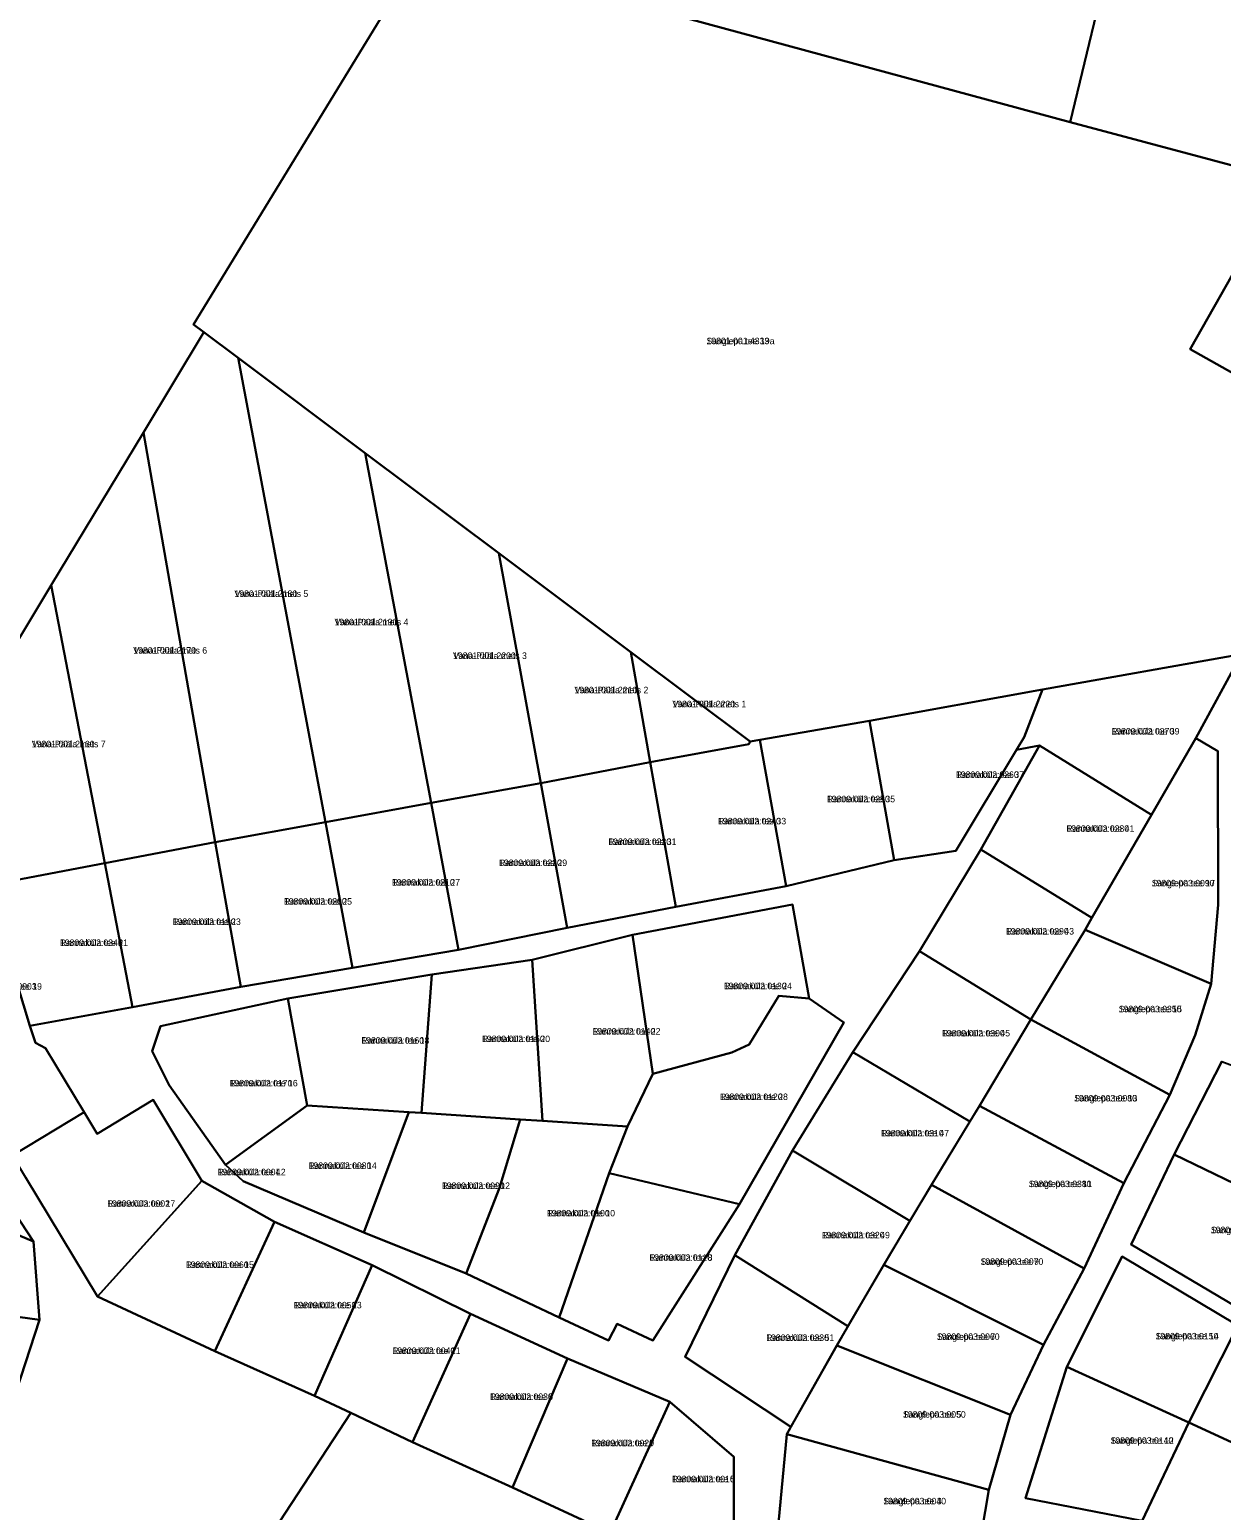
# Model space of a CAD drawing. Extents: x 516875 to 535633, y 6574491 to 6593094.
# Drawn here: x 520561.2 to 520836.7, y 6589652.4 to 6589994.6 of the extents above; entities that cross this region are included whole.
import ezdxf

# ---------------------------------------------------------------- set-up
doc = ezdxf.new("R2010")
doc.units = 0
for name, color, linetype in [('L_AADRESS', 7, 'Continuous'), ('PIIR', 7, 'Continuous'), ('TUNNUS', 7, 'Continuous')]:
    doc.layers.add(name, color=color, linetype=linetype)

msp = doc.modelspace()

# ---------------------------------------------------------------- linework, layer by layer
at = {"layer": 'PIIR'}
for points in [[(520972.97, 6590506), (521017.94, 6590380), (520943.67, 6590300.84), (520924.31, 6590299.46), (520898.89, 6590297.64), (520871.52, 6590295.69), (520865.36, 6590295.25), (520842.4, 6590293.61), (520818.5, 6590291.89), (520796.8, 6590254.57), (520656.14, 6590012.73), (520652.47, 6590013.72), (520599.13, 6589926.46), (520601.53, 6589924.66), (520587.57, 6589901.46), (520566.24, 6589866.18), (520544.87, 6589830.8)], [(520779.65, 6589637.54), (520782.94, 6589657.11), (520787.98, 6589674.41), (520795.57, 6589690.65), (520804.96, 6589708.27), (520814.17, 6589727.96), (520824.79, 6589748.39), (520830.66, 6589762.19), (520834.31, 6589774.07), (520835.99, 6589792.35), (520835.89, 6589827.87), (520830.79, 6589830.84), (520841.36, 6589850.29)], [(520724.04, 6589634.2), (520724.05, 6589664.77), (520709.22, 6589677.46), (520685.6, 6589687.46), (520663.13, 6589697.81), (520640.44, 6589709.04), (520617.81, 6589719.05), (520601.02, 6589728.57), (520589.78, 6589747.22), (520576.85, 6589739.39), (520573.84, 6589744.39), (520564.93, 6589759.22), (520562.6, 6589760.43), (520561.29, 6589764.38), (520585.05, 6589768.66), (520610.02, 6589773.34), (520635.88, 6589777.76), (520660.38, 6589781.96), (520685.48, 6589787.03), (520710.6, 6589791.89), (520736.09, 6589796.6), (520761.05, 6589802.65), (520775.32, 6589804.77), (520789.35, 6589828.12), (520794.65, 6589829.12), (520781.13, 6589805.1), (520766.94, 6589781.58), (520751.53, 6589758.29), (520737.61, 6589735.58), (520724.25, 6589711.37), (520712.8, 6589687.89), (520737.21, 6589671.68), (520736.26, 6589669.98), (520733.89, 6589644.51)], [(520555.93, 6589673.23), (520563.51, 6589696.39), (520562.16, 6589714.48), (520516.64, 6589783.8)], [(520836.81, 6589756.1), (520825.8, 6589734.61), (520815.83, 6589713.79), (520842.1, 6589698.25)], [(520560.3, 6589729.38), (520576.89, 6589701.76), (520604.08, 6589689.19), (520627.09, 6589678.87), (520635.48, 6589674.89), (520617.65, 6589647.69), (520602.23, 6589624.16), (520584.47, 6589593.13), (520580.8, 6589591.47), (520594.87, 6589556.89), (520608.46, 6589526.29), (520616.54, 6589521.14), (520611.08, 6589513.87), (520604.29, 6589520), (520594.99, 6589542.86), (520575.63, 6589590.44), (520553.77, 6589598.26)], [(520840.52, 6589695.13), (520813.76, 6589711.07), (520800.95, 6589685.54), (520791.41, 6589655.19), (520818.41, 6589649.98)]]:
    msp.add_lwpolyline(points, dxfattribs=at)
for points in [[(520796.8, 6590254.57), (520820.98, 6590255.41), (520822.81, 6590228.47), (520857.33, 6590230.68), (520864.64, 6590231.17), (520883.39, 6590232.72), (520889.49, 6590233.23), (520911.08, 6590235), (520913.85, 6590235.23), (520913.68, 6590217.02), (520913.48, 6590192.25), (520913.38, 6590165.33), (520912.67, 6590159.39), (520912.51, 6590122.84), (520913.01, 6590100.58), (520912.79, 6590085.78), (520912.31, 6590071.54), (520824.96, 6590069.29), (520801.74, 6589973.23), (520656.14, 6590012.73)], [(520801.74, 6589973.23), (520824.96, 6590069.29), (520912.31, 6590071.54), (520912.53, 6590070.3), (520912.35, 6590047.34), (520912.17, 6590025.02), (520931.67, 6590006.39), (520896.53, 6589947.83), (520851.66, 6589959.86)], [(520652.47, 6590013.72), (520656.14, 6590012.73), (520801.74, 6589973.23), (520851.66, 6589959.86), (520829.51, 6589920.73), (520868.75, 6589898.67), (520841.36, 6589850.29), (520795.36, 6589842.1), (520755.36, 6589834.88), (520730.05, 6589830.47), (520727.75, 6589830.09), (520700.2, 6589850.72), (520669.72, 6589873.59), (520638.79, 6589896.75), (520609.43, 6589918.74), (520601.53, 6589924.66), (520599.13, 6589926.46)], [(520829.51, 6589920.73), (520851.66, 6589959.86), (520896.53, 6589947.83), (520868.75, 6589898.67)], [(520587.57, 6589901.46), (520601.53, 6589924.66), (520609.43, 6589918.74), (520629.59, 6589811.43), (520604.16, 6589806.8)], [(520609.43, 6589918.74), (520638.79, 6589896.75), (520654.03, 6589815.87), (520629.59, 6589811.43)], [(520566.24, 6589866.18), (520587.57, 6589901.46), (520604.16, 6589806.8), (520578.62, 6589801.99)], [(520638.79, 6589896.75), (520669.72, 6589873.59), (520679.43, 6589820.47), (520654.03, 6589815.87)], [(520669.72, 6589873.59), (520700.2, 6589850.72), (520704.64, 6589825.27), (520679.43, 6589820.47)], [(520544.87, 6589830.8), (520566.24, 6589866.18), (520578.62, 6589801.99), (520551.44, 6589796.77)], [(520700.2, 6589850.72), (520727.75, 6589830.09), (520727.46, 6589829.45), (520704.64, 6589825.27)], [(520841.36, 6589850.29), (520830.79, 6589830.84), (520820.54, 6589813.09), (520794.65, 6589829.12), (520789.35, 6589828.12), (520791.12, 6589831.09), (520795.36, 6589842.1)], [(520755.36, 6589834.88), (520795.36, 6589842.1), (520791.12, 6589831.09), (520789.35, 6589828.12), (520775.32, 6589804.77), (520761.05, 6589802.65)], [(520755.36, 6589834.88), (520761.05, 6589802.65), (520736.09, 6589796.6), (520730.05, 6589830.47)], [(520704.64, 6589825.27), (520727.46, 6589829.45), (520727.75, 6589830.09), (520730.05, 6589830.47), (520736.09, 6589796.6), (520710.6, 6589791.89)], [(520835.89, 6589827.87), (520835.99, 6589792.35), (520834.31, 6589774.07), (520805.24, 6589786.58), (520806.8, 6589789.28), (520820.54, 6589813.09), (520830.79, 6589830.84)], [(520794.65, 6589829.12), (520820.54, 6589813.09), (520806.8, 6589789.28), (520781.13, 6589805.1)], [(520679.43, 6589820.47), (520704.64, 6589825.27), (520710.6, 6589791.89), (520685.48, 6589787.03)], [(520654.03, 6589815.87), (520679.43, 6589820.47), (520685.48, 6589787.03), (520660.38, 6589781.96)], [(520629.59, 6589811.43), (520654.03, 6589815.87), (520660.38, 6589781.96), (520635.88, 6589777.76)], [(520604.16, 6589806.8), (520629.59, 6589811.43), (520635.88, 6589777.76), (520610.02, 6589773.34)], [(520578.62, 6589801.99), (520604.16, 6589806.8), (520610.02, 6589773.34), (520585.05, 6589768.66)], [(520806.8, 6589789.28), (520805.24, 6589786.58), (520792.66, 6589765.81), (520766.94, 6589781.58), (520781.13, 6589805.1)], [(520551.44, 6589796.77), (520578.62, 6589801.99), (520585.05, 6589768.66), (520561.29, 6589764.38)], [(520522.86, 6589791.34), (520551.44, 6589796.77), (520561.29, 6589764.38), (520562.6, 6589760.43), (520564.93, 6589759.22), (520573.84, 6589744.39), (520557.31, 6589734.36), (520545.91, 6589753.32)], [(520591.52, 6589764.27), (520589.56, 6589758.53), (520593.52, 6589750.66), (520606.48, 6589732.23), (520610.56, 6589728.49), (520638.46, 6589716.61), (520662.17, 6589707.14), (520683.67, 6589696.97), (520695.03, 6589691.6), (520697.01, 6589695.46), (520705.31, 6589691.64), (520725.3, 6589723.15), (520749.46, 6589765.09), (520741.39, 6589770.64), (520737.61, 6589792.39), (520700.58, 6589785.36), (520677.4, 6589779.61), (520654.23, 6589776.23), (520620.9, 6589770.71)], [(520737.61, 6589792.39), (520741.39, 6589770.64), (520734.45, 6589771.26), (520727.55, 6589760.05), (520723.57, 6589758.2), (520705.28, 6589753.26), (520700.58, 6589785.36)], [(520700.58, 6589785.36), (520705.28, 6589753.26), (520699.47, 6589741.06), (520679.76, 6589742.38), (520677.4, 6589779.61)], [(520834.31, 6589774.07), (520830.66, 6589762.19), (520824.79, 6589748.39), (520792.66, 6589765.81), (520805.24, 6589786.58)], [(520516.64, 6589783.8), (520562.16, 6589714.48), (520512.11, 6589735.51), (520492.22, 6589743.86), (520487.93, 6589745.66)], [(520677.4, 6589779.61), (520679.76, 6589742.38), (520674.62, 6589742.67), (520651.84, 6589744.24), (520654.23, 6589776.23)], [(520751.53, 6589758.29), (520766.94, 6589781.58), (520792.66, 6589765.81), (520780.76, 6589745.89), (520778.55, 6589742.24)], [(520654.23, 6589776.23), (520651.84, 6589744.24), (520648.85, 6589744.39), (520625.38, 6589745.98), (520620.9, 6589770.71)], [(520620.9, 6589770.71), (520625.38, 6589745.98), (520606.48, 6589732.23), (520593.52, 6589750.66), (520589.56, 6589758.53), (520591.52, 6589764.27)], [(520705.28, 6589753.26), (520723.57, 6589758.2), (520727.55, 6589760.05), (520734.45, 6589771.26), (520741.39, 6589770.64), (520749.46, 6589765.09), (520725.3, 6589723.15), (520695.17, 6589730.29), (520699.47, 6589741.06)], [(520824.79, 6589748.39), (520814.17, 6589727.96), (520780.76, 6589745.89), (520792.66, 6589765.81)], [(520737.61, 6589735.58), (520751.53, 6589758.29), (520778.55, 6589742.24), (520769.68, 6589727.59), (520764.73, 6589719.31)], [(520866.63, 6589744.96), (520853.82, 6589721.06), (520825.8, 6589734.61), (520836.81, 6589756.1)], [(520557.31, 6589734.36), (520573.84, 6589744.39), (520576.85, 6589739.39), (520589.78, 6589747.22), (520601.02, 6589728.57), (520576.89, 6589701.76), (520560.3, 6589729.38)], [(520625.38, 6589745.98), (520648.85, 6589744.39), (520638.46, 6589716.61), (520610.56, 6589728.49), (520606.48, 6589732.23)], [(520651.84, 6589744.24), (520674.62, 6589742.67), (520669.84, 6589726.94), (520662.17, 6589707.14), (520638.46, 6589716.61), (520648.85, 6589744.39)], [(520814.17, 6589727.96), (520804.96, 6589708.27), (520769.68, 6589727.59), (520780.76, 6589745.89)], [(520679.76, 6589742.38), (520699.47, 6589741.06), (520695.17, 6589730.29), (520683.67, 6589696.97), (520662.17, 6589707.14), (520669.84, 6589726.94), (520674.62, 6589742.67)], [(520502.17, 6589706.37), (520512.11, 6589735.51), (520562.16, 6589714.48), (520563.51, 6589696.39), (520501.68, 6589704.95)], [(520724.25, 6589711.37), (520737.61, 6589735.58), (520764.73, 6589719.31), (520758.65, 6589709.13), (520750.37, 6589694.91)], [(520853.82, 6589721.06), (520842.1, 6589698.25), (520815.83, 6589713.79), (520825.8, 6589734.61)], [(520617.81, 6589719.05), (520604.08, 6589689.19), (520576.89, 6589701.76), (520601.02, 6589728.57)], [(520725.3, 6589723.15), (520705.31, 6589691.64), (520697.01, 6589695.46), (520695.03, 6589691.6), (520683.67, 6589696.97), (520695.17, 6589730.29)], [(520804.96, 6589708.27), (520795.57, 6589690.65), (520758.65, 6589709.13), (520769.68, 6589727.59)], [(520640.44, 6589709.04), (520627.09, 6589678.87), (520604.08, 6589689.19), (520617.81, 6589719.05)], [(520724.25, 6589711.37), (520750.37, 6589694.91), (520747.8, 6589690.49), (520737.21, 6589671.68), (520712.8, 6589687.89)], [(520840.52, 6589695.13), (520829.16, 6589672.69), (520800.95, 6589685.54), (520813.76, 6589711.07)], [(520663.13, 6589697.81), (520649.7, 6589668.13), (520635.48, 6589674.89), (520627.09, 6589678.87), (520640.44, 6589709.04)], [(520795.57, 6589690.65), (520787.98, 6589674.41), (520747.8, 6589690.49), (520758.65, 6589709.13)], [(520501.2, 6589703.53), (520501.68, 6589704.95), (520563.51, 6589696.39), (520555.93, 6589673.23), (520494.16, 6589682.9)], [(520685.6, 6589687.46), (520672.88, 6589657.69), (520649.7, 6589668.13), (520663.13, 6589697.81)], [(520843.48, 6589695.59), (520869.79, 6589683.57), (520856.41, 6589661.21), (520855.91, 6589660.36), (520829.16, 6589672.69), (520840.52, 6589695.13)], [(520787.98, 6589674.41), (520782.94, 6589657.11), (520736.26, 6589669.98), (520747.8, 6589690.49)], [(520709.22, 6589677.46), (520695.39, 6589647.19), (520672.88, 6589657.69), (520685.6, 6589687.46)], [(520829.16, 6589672.69), (520818.41, 6589649.98), (520791.41, 6589655.19), (520800.95, 6589685.54)], [(520724.05, 6589664.77), (520724.04, 6589634.2), (520695.39, 6589647.19), (520709.22, 6589677.46)], [(520617.65, 6589647.69), (520635.48, 6589674.89), (520649.7, 6589668.13), (520672.88, 6589657.69), (520695.39, 6589647.19), (520724.04, 6589634.2), (520723.65, 6589632.52), (520721.87, 6589624.79), (520689.63, 6589631.99), (520652.35, 6589642.27)], [(520855.91, 6589660.36), (520842.95, 6589639.45), (520818.25, 6589646.57), (520818.41, 6589649.98), (520829.16, 6589672.69)], [(520782.94, 6589657.11), (520779.65, 6589637.54), (520771.43, 6589639.44), (520755.18, 6589642.64), (520733.89, 6589644.51), (520736.26, 6589669.98)]]:
    msp.add_lwpolyline(points, close=True, dxfattribs=at)

# ---------------------------------------------------------------- texts
at = {"layer": 'L_AADRESS'}
for s, p in [('Sanglepa tee 19a', (520717.69, 6589921.9)), ('Vana-Pääla mets 5', (520608.58, 6589863.49)), ('Vana-Pääla mets 4', (520631.73, 6589856.93)), ('Vana-Pääla mets 6', (520585.2, 6589850.38)), ('Vana-Pääla mets 3', (520659.11, 6589849.16)), ('Vana-Pääla mets 2', (520687.18, 6589841.22)), ('Vana-Pääla mets 1', (520709.81, 6589837.99)), ('Rannaküla tee 39', (520811.3, 6589831.69)), ('Vana-Pääla mets 7', (520561.74, 6589828.74)), ('Rannaküla tee 37', (520775.36, 6589821.66)), ('Rannaküla tee 35', (520745.55, 6589816.03)), ('Rannaküla tee 33', (520720.37, 6589810.92)), ('Rannaküla tee 41', (520800.87, 6589809.2)), ('Rannaküla tee 31', (520695.02, 6589806.16)), ('Rannaküla tee 29', (520669.75, 6589801.29)), ('Rannaküla tee 27', (520644.99, 6589796.77)), ('Sanglepa tee 17', (520820.62, 6589796.59)), ('Rannaküla tee 25', (520620.02, 6589792.37)), ('Rannaküla tee 23', (520594.32, 6589787.67)), ('Rannaküla tee 43', (520786.92, 6589785.46)), ('Rannaküla tee 21', (520568.24, 6589782.82)), ('Rannaküla tee 19', (520548.35, 6589772.72)), ('Rannaküla tee 24', (520721.71, 6589772.83)), ('Sanglepa tee 15', (520812.98, 6589767.49)), ('Rannaküla tee 18', (520637.92, 6589760.24)), ('Rannaküla tee 20', (520665.8, 6589760.6)), ('Rannaküla tee 22', (520691.34, 6589762.34)), ('Rannaküla tee 45', (520772.13, 6589761.91)), ('Rannaküla tee 16', (520607.47, 6589750.36)), ('Rannaküla tee 28', (520720.78, 6589747.21)), ('Sanglepa tee 13', (520802.68, 6589746.88)), ('Rannaküla tee 47', (520758.03, 6589738.8)), ('Rannaküla tee L2', (520604.69, 6589729.82)), ('Rannaküla tee 14', (520625.73, 6589731.29)), ('Rannaküla tee 12', (520656.54, 6589726.65)), ('Sanglepa tee 11', (520792.18, 6589727.08)), ('Rannaküla tee 17', (520579.17, 6589722.54)), ('Rannaküla tee 10', (520680.82, 6589720.31)), ('Rannaküla tee 49', (520744.35, 6589715.24)), ('Sanglepa tee 20', (520834.27, 6589716.43)), ('Rannaküla tee 15', (520597.35, 6589708.4)), ('Rannaküla tee 8', (520704.48, 6589710.05)), ('Sanglepa tee 9', (520781.04, 6589709.12)), ('Rannaküla tee 13', (520622.26, 6589699.06)), ('Rannaküla tee 51', (520731.49, 6589691.53)), ('Sanglepa tee 7', (520770.94, 6589691.77)), ('Sanglepa tee 14', (520821.5, 6589691.88)), ('Rannaküla tee 11', (520645.11, 6589688.52)), ('Rannaküla tee 9', (520667.65, 6589677.89)), ('Sanglepa tee 5', (520763.11, 6589673.8)), ('Rannaküla tee 7', (520691.05, 6589667.18)), ('Sanglepa tee 12', (520811.09, 6589667.76)), ('Rannaküla tee 5', (520709.72, 6589658.86)), ('Sanglepa tee 3', (520758.56, 6589653.76))]:
    msp.add_text(s, height=1.5, dxfattribs=at).set_placement(p)
at = {"layer": 'TUNNUS'}
for s, p in [('19801:001:4333', (520717.69, 6589921.9)), ('19801:001:2180', (520608.58, 6589863.49)), ('19801:001:2190', (520631.73, 6589856.93)), ('19801:001:2170', (520585.2, 6589850.38)), ('19801:001:2200', (520659.11, 6589849.16)), ('19801:001:2210', (520687.18, 6589841.22)), ('19801:001:2220', (520709.81, 6589837.99)), ('19809:002:0270', (520811.3, 6589831.69)), ('19801:001:2160', (520561.74, 6589828.74)), ('19809:002:0260', (520775.36, 6589821.66)), ('19809:002:0250', (520745.55, 6589816.03)), ('19809:002:0240', (520720.37, 6589810.92)), ('19809:002:0280', (520800.87, 6589809.2)), ('19809:002:0230', (520695.02, 6589806.16)), ('19809:002:0220', (520669.75, 6589801.29)), ('19809:002:0210', (520644.99, 6589796.77)), ('19809:003:0090', (520820.62, 6589796.59)), ('19809:002:0200', (520620.02, 6589792.37)), ('19809:002:0190', (520594.32, 6589787.67)), ('19809:002:0290', (520786.92, 6589785.46)), ('19809:002:0340', (520568.24, 6589782.82)), ('19809:002:0003', (520548.35, 6589772.72)), ('19809:002:0130', (520721.71, 6589772.83)), ('19809:003:0350', (520812.98, 6589767.49)), ('19809:002:0160', (520637.92, 6589760.24)), ('19809:002:0150', (520665.8, 6589760.6)), ('19809:002:0140', (520691.34, 6589762.34)), ('19809:002:0300', (520772.13, 6589761.91)), ('19809:002:0170', (520607.47, 6589750.36)), ('19809:002:0120', (520720.78, 6589747.21)), ('19809:003:0080', (520802.68, 6589746.88)), ('19809:002:0310', (520758.03, 6589738.8)), ('19809:002:0004', (520604.69, 6589729.82)), ('19809:002:0080', (520625.73, 6589731.29)), ('19809:002:0090', (520656.54, 6589726.65)), ('19809:003:0380', (520792.18, 6589727.08)), ('19809:002:0002', (520579.17, 6589722.54)), ('19809:002:0100', (520680.82, 6589720.31)), ('19809:002:0320', (520744.35, 6589715.24)), ('19809:003:0180', (520834.27, 6589716.43)), ('19809:002:0060', (520597.35, 6589708.4)), ('19809:002:0110', (520704.48, 6589710.05)), ('19809:003:0070', (520781.04, 6589709.12)), ('19809:002:0050', (520622.26, 6589699.06)), ('19809:002:0330', (520731.49, 6589691.53)), ('19809:003:0060', (520770.94, 6589691.77)), ('19809:003:0150', (520821.5, 6589691.88)), ('19809:002:0040', (520645.11, 6589688.52)), ('19809:002:0030', (520667.65, 6589677.89)), ('19809:003:0050', (520763.11, 6589673.8)), ('19809:003:0140', (520811.09, 6589667.76)), ('19809:002:0020', (520691.05, 6589667.18)), ('19809:002:0010', (520709.72, 6589658.86)), ('19809:003:0040', (520758.56, 6589653.76))]:
    msp.add_text(s, height=1.5, dxfattribs=at).set_placement(p)

doc.saveas('drawing.dxf')
